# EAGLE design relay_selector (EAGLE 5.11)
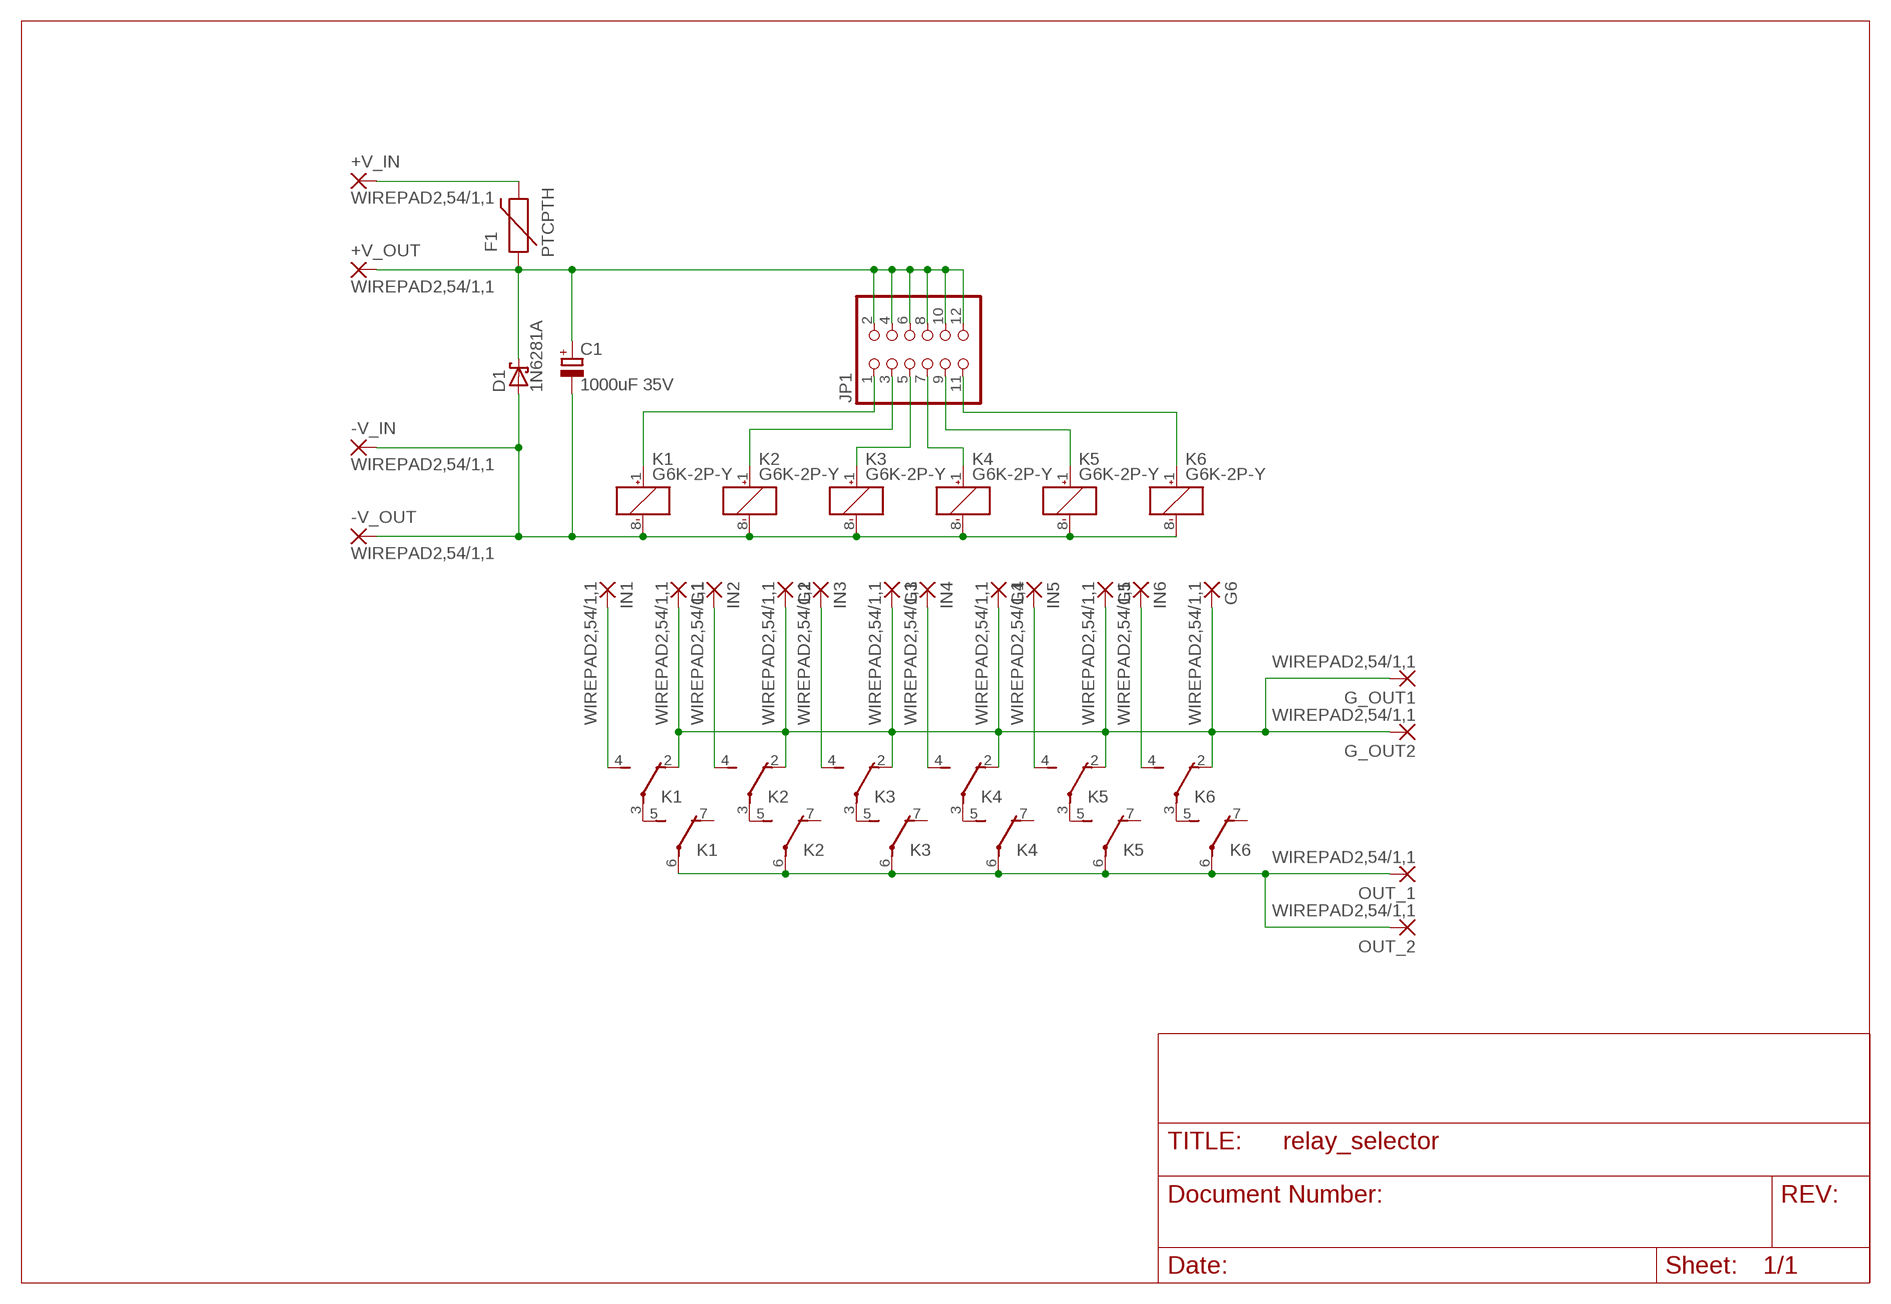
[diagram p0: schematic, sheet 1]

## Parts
+V_IN  WIREPAD2,54/1,1  [2,54/1,1]
+V_OUT  WIREPAD2,54/1,1  [2,54/1,1]
-V_IN  WIREPAD2,54/1,1  [2,54/1,1]
-V_OUT  WIREPAD2,54/1,1  [2,54/1,1]
C1  1000uF 35V  CPOL-EUE5-13  [E5-13]
D1  1N6281A  1N6267A  [C4111-15]
F1  PTCPTH  [PTC]
G1  WIREPAD2,54/1,1  [2,54/1,1]
G2  WIREPAD2,54/1,1  [2,54/1,1]
G3  WIREPAD2,54/1,1  [2,54/1,1]
G4  WIREPAD2,54/1,1  [2,54/1,1]
G5  WIREPAD2,54/1,1  [2,54/1,1]
G6  WIREPAD2,54/1,1  [2,54/1,1]
G_OUT1  WIREPAD2,54/1,1  [2,54/1,1]
G_OUT2  WIREPAD2,54/1,1  [2,54/1,1]
IN1  WIREPAD2,54/1,1  [2,54/1,1]
IN2  WIREPAD2,54/1,1  [2,54/1,1]
IN3  WIREPAD2,54/1,1  [2,54/1,1]
IN4  WIREPAD2,54/1,1  [2,54/1,1]
IN5  WIREPAD2,54/1,1  [2,54/1,1]
IN6  WIREPAD2,54/1,1  [2,54/1,1]
JP1  PINHD-2X6  [2X06]
K1  G6K-2P-Y  [G6K-2P-Y]
K2  G6K-2P-Y  [G6K-2P-Y]
K3  G6K-2P-Y  [G6K-2P-Y]
K4  G6K-2P-Y  [G6K-2P-Y]
K5  G6K-2P-Y  [G6K-2P-Y]
K6  G6K-2P-Y  [G6K-2P-Y]
OUT_1  WIREPAD2,54/1,1  [2,54/1,1]
OUT_2  WIREPAD2,54/1,1  [2,54/1,1]

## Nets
N$1: +V_IN.1(P) F1.P$2
N$2: +V_OUT.1(P) C1.+ D1.C F1.P$1 JP1.2 JP1.4 JP1.6 JP1.8 JP1.10 JP1.12
N$3: -V_IN.1(P) -V_OUT.1(P) C1.- D1.A K1.8(1:-) K2.8(1:-) K3.8(1:-) K4.8(1:-) K5.8(1:-) K6.8(1:-)
N$4: JP1.5 K3.1(1:+)
N$5: JP1.3 K2.1(1:+)
N$6: JP1.1 K1.1(1:+)
N$7: JP1.7 K4.1(1:+)
N$8: JP1.9 K5.1(1:+)
N$9: JP1.11 K6.1(1:+)
N$10: IN1.1(P) K1.4(2:S)
N$12: IN2.1(P) K2.4(2:S)
N$13: G1.1(P) G2.1(P) G3.1(P) G4.1(P) G5.1(P) G6.1(P) G_OUT1.1(P) G_OUT2.1(P) K1.2(2:O) K2.2(2:O) K3.2(2:O) K4.2(2:O) K5.2(2:O) K6.2(2:O)
N$14: IN6.1(P) K6.4(2:S)
N$16: IN5.1(P) K5.4(2:S)
N$18: IN4.1(P) K4.4(2:S)
N$20: IN3.1(P) K3.4(2:S)
N$22: K1.3(2:P) K1.5(3:S)
N$23: K2.3(2:P) K2.5(3:S)
N$24: K3.3(2:P) K3.5(3:S)
N$25: K4.3(2:P) K4.5(3:S)
N$26: K5.3(2:P) K5.5(3:S)
N$27: K6.3(2:P) K6.5(3:S)
N$28: K1.6(3:P) K2.6(3:P) K3.6(3:P) K4.6(3:P) K5.6(3:P) K6.6(3:P) OUT_1.1(P) OUT_2.1(P)
Unconnected: K1.7(3:O) K2.7(3:O) K3.7(3:O) K4.7(3:O) K5.7(3:O) K6.7(3:O)

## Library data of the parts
+V_IN +V_OUT -V_IN -V_OUT G1-G6 G_OUT1 G_OUT2 IN1-IN6 OUT_1 OUT_2 = wirepad:WIREPAD: Wire PAD connect wire on PCB
C1 = rcl:CPOL-EU: POLARIZED CAPACITOR, European symbol
D1 = diode:1N6267A: DIODE
F1 = SparkFun:PTC: Resettable Fuse PTC
JP1 = pinhead:PINHD-2X6: PIN HEADER
K1-K6 = relay:G6K: Low Signal Relay oeiwcsnts1.omron.com/.. D20G6K0100.pdf; MF: OMRON COMPONENTS USA; MPN: G6K-2P-Y DC12; OC_FARNELL: 3937276; OC_NEWARK: 34C3464

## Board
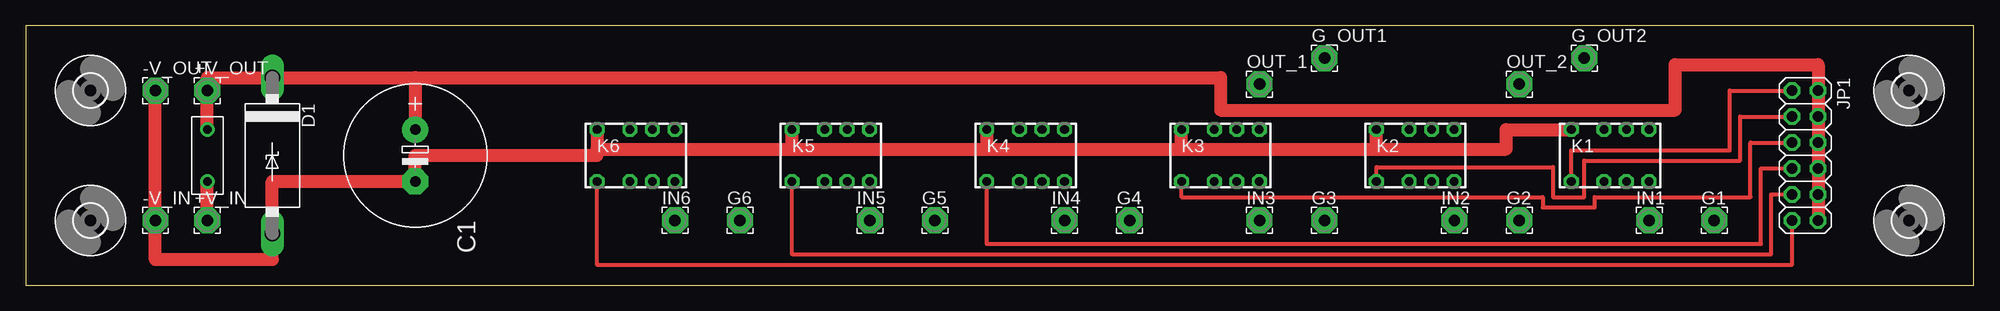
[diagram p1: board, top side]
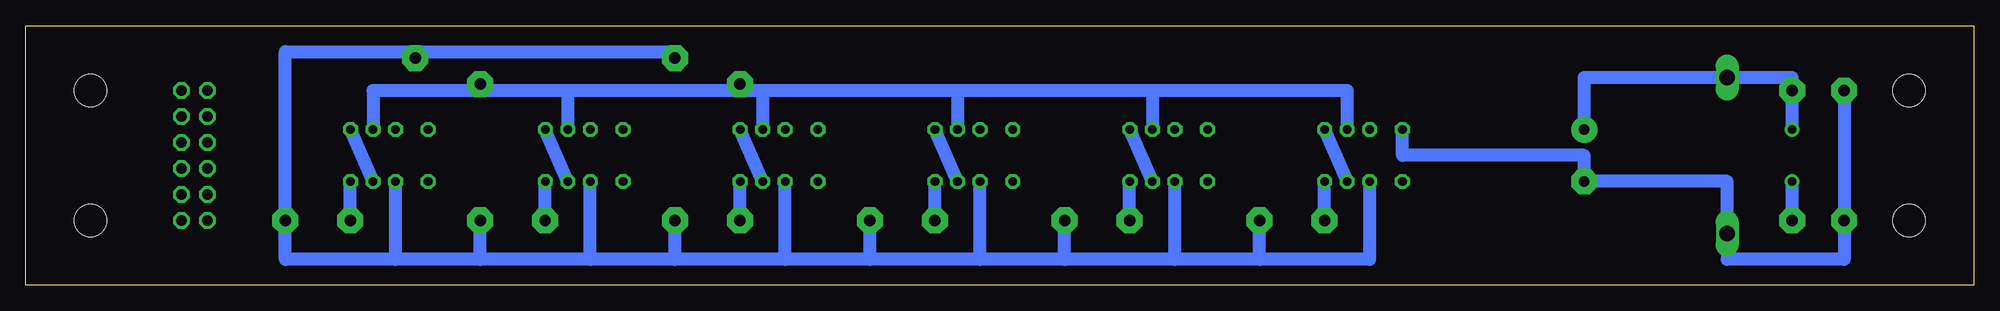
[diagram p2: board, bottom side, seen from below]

Size 190.5 x 25.4 mm. Coordinates in mm from the lower left corner, seen from the top.
Outline: 0,0 190.5,0 190.5,25.4 0,25.4 0,0
Copper layers (1*16): Top 0.035mm / dielectric 1.5mm / Bottom 0.035mm
Design rules "SparkFun": minimum track width 8mil, minimum drill 20mil, track to track 8mil, track to pad 8mil, pad to pad 8mil, via to via 8mil, smd to smd 8mil, copper to edge 10mil, drill to drill 8mil, minimum pad ring 12mil, minimum via ring 10mil, stop-mask expansion 4mil, vias tented up to drill 25mil, thermal gap 10mil

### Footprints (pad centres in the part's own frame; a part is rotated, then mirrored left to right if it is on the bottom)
2,54/1,1 = drill 1.118 pad 2.54 octagon: 1 0,0
E5-13 = drill 1.016 pad 2.54 round: + -2.54,0 | drill 1.016 pad 2.54 octagon: - 2.54,0
C4111-15 = drill 1.499 long: A 7.62,0; C -7.62,0
PTC = drill 0.8 round: P$1 -2.54,0; P$2 2.54,0
2X06 = drill 1.016 octagon: 1 -6.35,-1.27; 2 -6.35,1.27; 3 -3.81,-1.27; 4 -3.81,1.27; 5 -1.27,-1.27; 6 -1.27,1.27; 7 1.27,-1.27; 8 1.27,1.27; 9 3.81,-1.27; 10 3.81,1.27; 11 6.35,-1.27; 12 6.35,1.27
G6K-2P-Y = drill 0.85 octagon: 1 0,-2.54; 2 3.2,-2.54; 3 5.4,-2.54; 4 7.6,-2.54; 5 7.6,2.54; 6 5.4,2.54; 7 3.2,2.54; 8 0,2.54
3,2 = hole 3.2: 0,0

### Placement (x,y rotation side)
+V_IN  17.78,6.35 0 top
+V_OUT  17.78,19.05 0 top
-V_IN  12.7,6.35 0 top
-V_OUT  12.7,19.05 0 top
C1  38.1,12.7 270 top
D1  24.13,12.7 270 top
F1  17.78,12.7 270 top
G1  165.1,6.35 0 top
G2  146.05,6.35 0 top
G3  127,6.35 0 top
G4  107.95,6.35 0 top
G5  88.9,6.35 0 top
G6  69.85,6.35 0 top
G_OUT1  127,22.23 0 top
G_OUT2  152.4,22.23 0 top
IN1  158.75,6.35 0 top
IN2  139.7,6.35 0 top
IN3  120.65,6.35 0 top
IN4  101.6,6.35 0 top
IN5  82.55,6.35 0 top
IN6  63.5,6.35 0 top
JP1  173.99,12.7 270 top
K1  151.13,12.7 0 top
K2  132.08,12.7 0 top
K3  113.03,12.7 0 top
K4  93.98,12.7 0 top
K5  74.93,12.7 0 top
K6  55.88,12.7 0 top
OUT_1  120.65,19.68 0 top
OUT_2  146.05,19.68 0 top
U$1  [3,2]  6.35,19.05 0 top
U$2  [3,2]  6.35,6.35 0 top
U$3  [3,2]  184.15,6.35 0 top
U$4  [3,2]  184.15,19.05 0 top

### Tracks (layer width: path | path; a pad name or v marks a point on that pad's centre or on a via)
N$1
  Top 1.27: +V_IN.1 F1.P$2
  Bottom 1.27: +V_IN.1 F1.P$2
N$2
  Top 1.27: F1.P$1 17.78,20.32 38.1,20.32 | 38.1,20.32 C1.+ | 38.1,20.32 116.84,20.32 116.84,17.14 161.29,17.14 161.29,21.59 175.26,21.59 JP1.2 JP1.4 JP1.6 | JP1.6 175.26,12.7 | JP1.6 JP1.8 JP1.10 JP1.12
  Bottom 1.27: F1.P$1 +V_OUT.1 17.78,20.32 D1.C 38.1,20.32 C1.+
N$3
  Top 1.27: K6.8 55.88,13.34 | 55.88,13.34 74.93,13.34 | 74.93,13.34 93.98,13.34 | 93.98,13.34 113.03,13.34 | 113.03,13.34 132.08,13.34 | 132.08,13.34 144.78,13.34 144.78,15.24 K1.8 | 132.08,13.34 K2.8 | 113.03,13.34 K3.8 | 93.98,13.34 K4.8 | 74.93,13.34 K5.8 | 55.88,13.34 55.88,12.7 54.61,12.7 38.1,12.7 C1.- 24.13,10.16 D1.A 24.13,2.54 12.7,2.54 -V_OUT.1
  Bottom 1.27: -V_OUT.1 -V_IN.1 12.7,2.54 24.13,2.54 D1.A 24.13,10.16 C1.- 38.1,12.7 55.88,12.7 K6.8
N$4
  Top 0.406: JP1.5 168.66,13.97 168.66,8.64 153.42,8.64 153.42,7.62 148.34,7.62 148.34,8.64 113.03,8.64 K3.1
N$5
  Top 0.406: K2.1 132.08,11.56 149.35,11.56 149.35,8.64 152.4,8.64 152.4,12.19 167.64,12.19 167.64,16.51 JP1.3
N$6
  Top 0.406: K1.1 151.13,13.21 166.62,13.21 166.62,19.05 JP1.1
N$7
  Top 0.406: JP1.7 169.67,11.43 169.67,4.06 93.98,4.06 K4.1
N$8
  Top 0.406: JP1.9 170.69,8.89 170.69,3.05 74.93,3.05 K5.1
N$9
  Top 0.406: JP1.11 172.72,2.03 55.88,2.03 K6.1
N$10
  Bottom 1.27: IN1.1 158.75,10.16 K1.4
N$12
  Bottom 1.27: IN2.1 139.7,10.16 K2.4
N$13
  Bottom 1.27: 69.85,2.54 G6.1 | 78.13,2.54 88.9,2.54 | 88.9,2.54 97.18,2.54 | 116.23,2.54 127,2.54 | 127,2.54 135.28,2.54 | 146.05,2.54 154.33,2.54 | 146.05,2.54 G2.1 | 127,2.54 G3.1 | 107.95,2.54 G4.1 | 88.9,2.54 G5.1 | 152.4,22.86 127,22.86 G_OUT1.1 | K6.2 59.08,2.54 69.85,2.54 | 78.13,2.54 K5.2 | 69.85,2.54 78.13,2.54 | 97.18,2.54 K4.2 | 97.18,2.54 107.95,2.54 | 116.23,2.54 K3.2 | 107.95,2.54 116.23,2.54 | 135.28,2.54 K2.2 | 135.28,2.54 146.05,2.54 | 154.33,2.54 K1.2 | 154.33,2.54 165.1,2.54 G1.1 165.1,22.86 152.4,22.86 | 152.4,22.86 G_OUT2.1
N$14
  Bottom 1.27: IN6.1 63.5,10.16 K6.4
N$16
  Bottom 1.27: IN5.1 82.55,10.16 K5.4
N$18
  Bottom 1.27: IN4.1 101.6,10.16 K4.4
N$20
  Bottom 1.27: IN3.1 120.65,10.16 K3.4
N$22
  Bottom 1.27: K1.3 K1.5
N$23
  Bottom 1.27: K2.3 K2.5
N$24
  Bottom 1.27: K3.3 K3.5
N$25
  Bottom 1.27: K4.3 K4.5
N$26
  Bottom 1.27: K5.3 K5.5
N$27
  Bottom 1.27: K6.3 K6.5
N$28
  Bottom 1.27: K6.6 61.28,19.05 80.33,19.05 | 118.43,19.05 120.65,19.05 | K1.6 156.53,19.05 146.05,19.05 | 137.48,19.05 146.05,19.05 | 146.05,19.05 OUT_2.1 | 137.48,19.05 K2.6 | 120.65,19.05 OUT_1.1 | 120.65,19.05 137.48,19.05 | 118.43,19.05 K3.6 | 99.38,19.05 118.43,19.05 | 99.38,19.05 K4.6 | 80.33,19.05 99.38,19.05 | 80.33,19.05 K5.6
